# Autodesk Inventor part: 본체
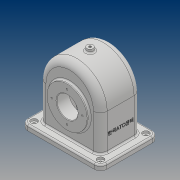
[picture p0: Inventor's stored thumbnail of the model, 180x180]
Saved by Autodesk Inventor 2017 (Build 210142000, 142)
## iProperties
Part Number: 본체
Material: 일반
Document SubType Name: Modeling
Designer: 20
Density: 1 g/cm^3
Appearance: 기본값
Author: 20
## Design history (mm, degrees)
sketch "스케치5"
  geometry: L1 (58, 13)-(58, -65); L2 (58, -65)-(-58, -65); L3 (-58, -65)-(-58, 13); A1 r 58 centre (0, 13) between (58, 13) and (-58, 13); 1 further point
  constraints: 6 end point, 2 point on circle, 2 tangent, 2 vertical, 1 centre point, 1 horizontal, 1 vertical alignment
  dimensions: "d13" = 116 diameter of A1; "d14" = 13 distance of point (0, 0) A1.centre; "d15" = 78 distance from line of L2 A1.centre
extrude "돌출4" new body sketch "스케치5" stored distance "d16" = 77; taper "d17" = 0 deg
sketch "스케치6"
  geometry: L1 (58, -65)-(58, 13) reference; L2 (-58, 13)-(-58, -65) reference; L3 (-52, -78)-(-52, 13); L4 (52, 13)-(52, -78); L5 (52, -78)-(-52, -78); A1 r 58 centre (0, 13) between (58, 13) and (-58, 13) reference; A2 r 52 centre (0, 13) between (52, 13) and (-52, 13); 1 further point
  constraints: 6 end point, 2 point on circle, 1 centre point, 1 horizontal, 2 other
  dimensions: "d18" = 6 radial gap between concentric circles of A1 A2; "d19" = 78 distance from line of L5 point (0, 0)
extrude "돌출5" cut sketch "스케치6" stored distance "d20" = 67; taper "d21" = 0 deg
sketch "스케치7"
  geometry: L1 (6, -72)-(6, -5) reference; L2 (110, -72)-(6, -72) reference; L3 (6, -5)-(110, -5) reference; L4 (110, -5)-(110, -72) reference; L5 (133, -93.5)-(-17, -93.5); L6 (-17, -93.5)-(-17, 16.5); L7 (-17, 16.5)-(133, 16.5); L8 (133, 16.5)-(133, -93.5); L9 (133, -93.5)-(-17, 16.5); L10 (-17, -93.5)-(133, 16.5); 1 further point
  constraints: 12 end point, 2 midpoint, 2 parallel, 1 horizontal, 1 perpendicular
  dimensions: "d22" = 110 distance of L5.end L6.end; "d23" = 150 distance of L6.end L7.end
extrude "돌출6" join sketch "스케치7" distance "d24" = 10; taper "d25" = 0 deg
sketch "스케치8"
  geometry: C1 r 38 at (0, 0); 1 further point
  constraints: 1 centre point, 1 coincident
  dimensions: "d26" = 76 diameter of C1
extrude "돌출7" join sketch "스케치8" distance "d27" = 10; taper "d28" = 0 deg
sketch "스케치10"
  geometry: C1 r 38 at (0, 0); 1 further point
  constraints: 1 centre point, 1 coincident
  dimensions: "d29" = 76 diameter of C1
extrude "돌출8" join sketch "스케치10" distance "d30" = 5; taper "d31" = 0 deg
sketch "스케치11"
  geometry: C1 r 28 at (0, 0); 1 further point
  constraints: 1 centre point, 1 coincident
  dimensions: "d32" = 56 diameter of C1
extrude "돌출9" join sketch "스케치11" distance "d33" = 14; taper "d34" = 0 deg
sketch "스케치13"
  geometry: 1 further point
feature "면 기울기1" dims angle "d35" = 40 deg
sketch "스케치15"
  geometry: C1 r 20 at (0, 0); 1 further point
  constraints: 1 centre point, 1 coincident
  dimensions: "d36" = 40 diameter of C1
extrude "돌출10" cut sketch "스케치15" distance "d37" = 500; taper "d38" = 0 deg
sketch "스케치17"
  geometry: 2 further points
  constraints: 1 vertical alignment
  dimensions: "d39" = 29 distance of point (0, 0) point (0, 29)
hole "구멍1" sketch "스케치17" at (0, 29) diameter "d40" = 3.242; stored, may be unused: countersink angle "d44" = 90 deg, drill point angle "d46" = 118 deg; dims "d41" = 8, "d42" = 4, "d43" = 2, "d45" = 10
sketch "스케치18"
  geometry: 2 further points
  constraints: 1 vertical alignment
  dimensions: "d50" = 29 distance of point (0, 0) point (0, -29)
hole "구멍2" sketch "스케치18" at (0, -29) diameter "d51" = 3.242; stored, may be unused: countersink angle "d55" = 90 deg, drill point angle "d57" = 118 deg; dims "d52" = 8, "d53" = 4, "d54" = 2, "d56" = 10
node "작업 평면1"
sketch "스케치19"
  geometry: C1 r 6 at (75, 55); 1 further point
  constraints: 1 centre point, 1 coincident
  dimensions: "d62" = 12 diameter of C1
extrude "돌출11" join sketch "스케치19" stored distance "d63" = 500; taper "d64" = 5 deg
hole "구멍3" diameter "d67" = 4.459; stored, may be unused: countersink angle "d71" = 90 deg, drill point angle "d73" = 0 deg; dims "d65" = 10, "d66" = 10, "d68" = 10, "d69" = 4, "d70" = 2, "d72" = 30
fillet "모깎기1" dims "d74" = 12
hole "구멍4" diameter "d77" = 5; stored, may be unused: countersink angle "d81" = 90 deg, drill point angle "d83" = 0 deg; dims "d75" = 10, "d76" = 10, "d78" = 10, "d79" = 12, "d80" = 4, "d82" = 30
sketch "스케치21"
  geometry: L1 (68, 0)-(0, 0) reference; L2 (78, -4.5)-(78, 81.5) reference; 2 further points
  constraints: 1 other
  dimensions: "d90" = 38.5 distance from line of L1 point (38, 38.5); "d91" = 40 distance from line of L2 point (38, 38.5)
feature "엠보싱1" sketch "스케치21" dims "d92" = 0.5, "d93" = 0
chamfer "모따기1" distance "d94" = 1; stored, may be unused: second distance "d95" = 2, angle "d96" = 45 deg
fillet "모깎기2" dims "d97" = 8
fillet "모깎기3" dims "d98" = 3
fillet "모깎기4" dims "d99" = 3
fillet "모깎기5" dims "d100" = 13
fillet "모깎기6" dims "d101" = 3
fillet "모깎기7" dims "d102" = 3
node "솔리드2"
pattern_circular "원형 패턴1" dims angle "d48" = 360 deg
pattern_circular "원형 패턴2" dims angle "d59" = 360 deg
pattern_linear "직사각형 패턴1" dims "d86" = 126, "d89" = 86
other parameters: "d61" = -142
